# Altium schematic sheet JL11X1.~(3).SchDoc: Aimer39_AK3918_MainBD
size 431 x 279 mm; Revision: 1.2.1; Release Date: 2014-05-28; SchModifyDate: 2020.11.1; PCBVersion: V1.0.0; PCBPartNumber: EVB_PHY_SZ18201; 版本号: V1.0.0
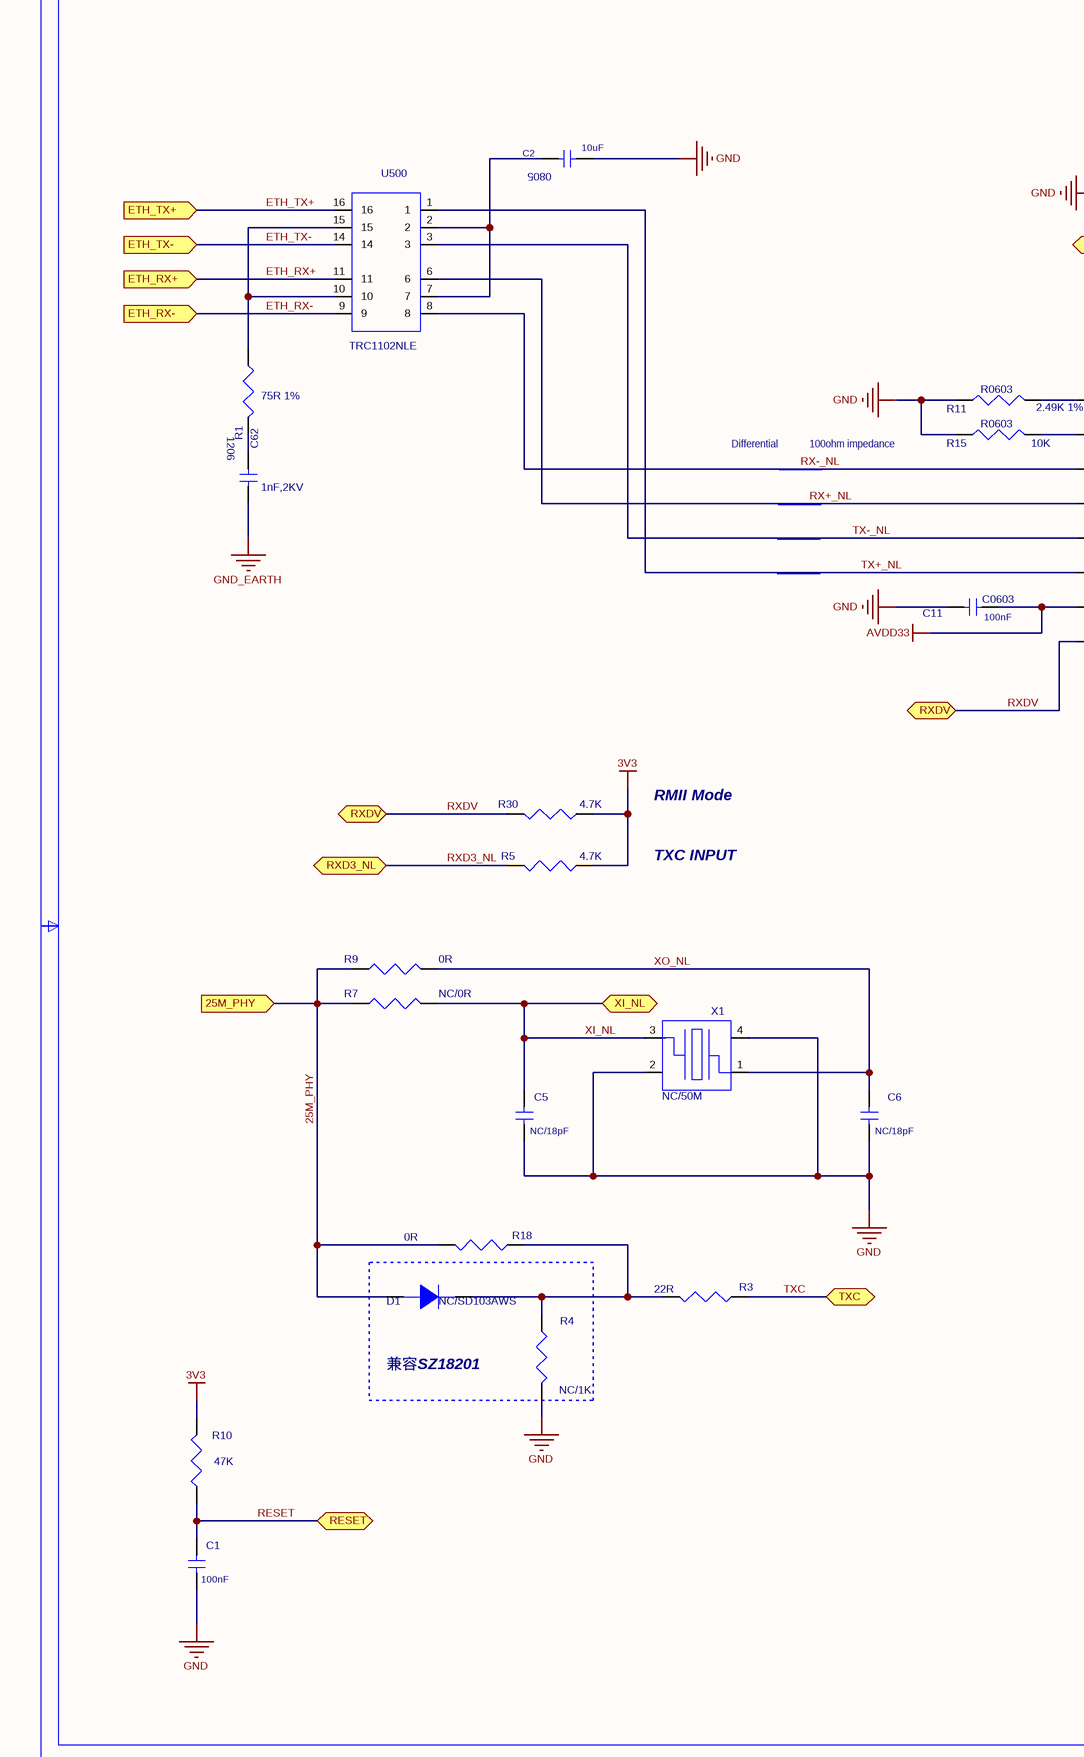
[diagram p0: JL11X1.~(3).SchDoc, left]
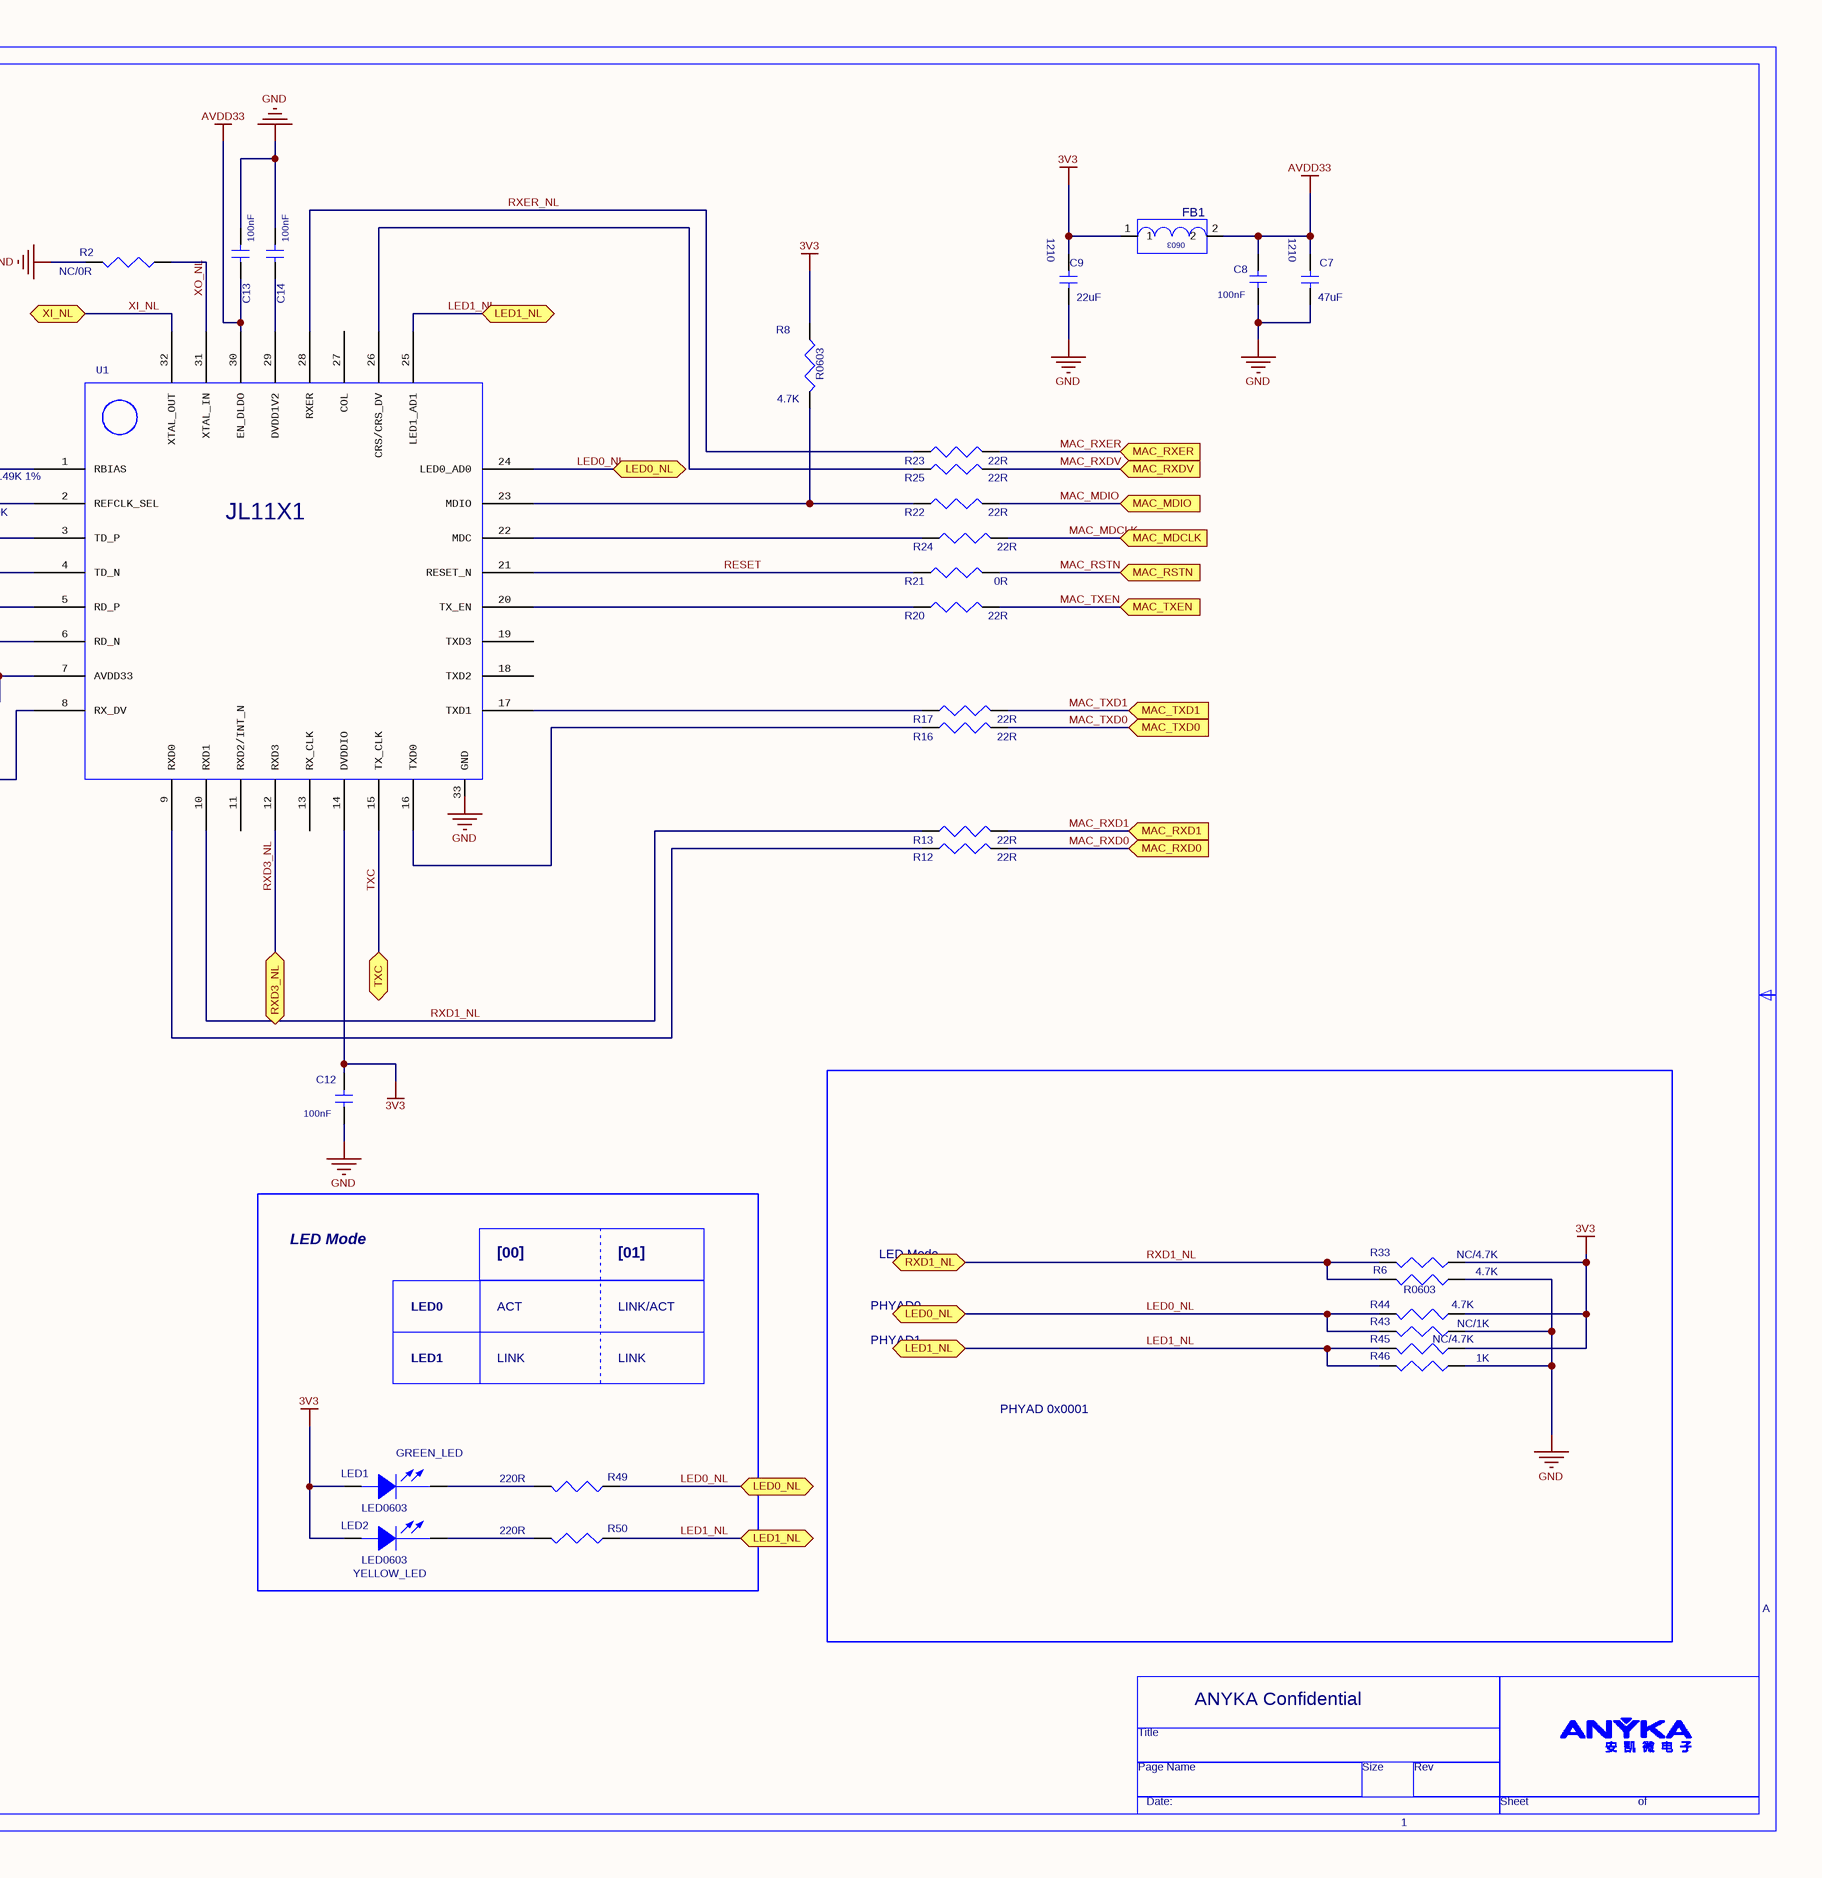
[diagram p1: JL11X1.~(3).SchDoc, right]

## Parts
C1  value 100nF  [C0603]  (hidden comment: C0603)
C2  value 10uF  [C0805]  (hidden comment: C0805)
C5  value NC/18pF  [C0603]  (hidden comment: C0603)
C6  value NC/18pF  [C0603]  (hidden comment: C0603)
C7  value 47uF  [C1210]  (hidden comment: C1210)
C8  value 100nF  [C0603]  (hidden comment: C0603)
C9  value 22uF  [C1210]  (hidden comment: C1210)
C11  C0603  value 100nF  [C0603]
C12  value 100nF  [C0603]  (hidden comment: C0603)
C13  value 100nF  [C0603]  (hidden comment: C0603)
C14  value 100nF  [C0603]  (hidden comment: C0603)
C62  value 1nF,2KV  [C1206]  (hidden comment: C1206)
D1  value NC/SD103AWS  [1N4148_SMD]  (hidden comment: DIODE)
FB1  FB0603  [FB0603]  (value not drawn)
LED1  value GREEN_LED  [LED0603]  (hidden comment: LED0603)
LED2  value YELLOW_LED  [LED0603]  (hidden comment: LED0603)
R1  value 75R 1%  [R0603]  (hidden comment: R0603)
R2  value NC/0R  [R0603]  (hidden comment: R0603)
R3  value 22R  [R0603]  (hidden comment: R0603)
R4  value NC/1K  [R0603]  (hidden comment: R0603)
R5  value 4.7K  [R0603]  (hidden comment: R0603)
R6  R0603  value 4.7K  [R0603]
R7  value NC/0R  [R0603]  (hidden comment: R0603)
R8  R0603  value 4.7K  [R0603]
R9  value 0R  [R0603]  (hidden comment: R0603)
R10  value 47K  [R0603]  (hidden comment: R0603)
R11  R0603  value 2.49K 1%  [R0603]
R12  value 22R  [R0603]  (hidden comment: R0603)
R13  value 22R  [R0603]  (hidden comment: R0603)
R15  R0603  value 10K  [R0603]
R16  value 22R  [R0603]  (hidden comment: R0603)
R17  value 22R  [R0603]  (hidden comment: R0603)
R18  value 0R  [R0603]  (hidden comment: R0603)
R20  value 22R  [R0603]  (hidden comment: R0603)
R21  value 0R  [R0603]  (hidden comment: R0603)
R22  value 22R  [R0603]  (hidden comment: R0603)
R23  value 22R  [R0603]  (hidden comment: R0603)
R24  value 22R  [R0603]  (hidden comment: R0603)
R25  value 22R  [R0603]  (hidden comment: R0603)
R30  value 4.7K  [R0603]  (hidden comment: R0603)
R33  value NC/4.7K  [R0603]  (hidden comment: R0603)
R43  value NC/1K  [R0603]  (hidden comment: R0603)
R44  value 4.7K  [R0603]  (hidden comment: R0603)
R45  value NC/4.7K  [R0603]  (hidden comment: R0603)
R46  value 1K  [R0603]  (hidden comment: R0603)
R49  value 220R  [R0603]  (hidden comment: R0603)
R50  value 220R  [R0603]  (hidden comment: R0603)
U1  JZ1101_QFN32_0MM5_5X5MM  [RTL8201F_QFN32_0MM5_5X5MM]  (value not drawn)
U500  TRC1102NLE  [TRC1102NLE]
X1  value NC/50M  [KSX23]  (hidden comment: KSX23)

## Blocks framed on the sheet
兼容SZ18201: D1 R4

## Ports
25M_PHY, ETH_RX+, ETH_RX-, ETH_TX+, ETH_TX-, LED0_NL (bidir), LED1_NL (bidir), MAC_MDCLK, MAC_MDIO, MAC_RSTN, MAC_RXD0, MAC_RXD1, MAC_RXDV, MAC_RXER, MAC_TXD0 (in), MAC_TXD1 (in), MAC_TXEN (in), RESET (bidir), RXD1_NL (bidir), RXD3_NL (bidir), RXDV (bidir), TXC (bidir), XI_NL (bidir)

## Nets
3V3: C9.1 C12.2 FB1.1 LED1.A LED2.A R5.2 R8.1 R10.2 R30.2 R33.2 R44.2 R45.2 U1.14(DVDDIO)
AVDD33: C7.1 C8.2 C11.2 C13.1 FB1.2 U1.7(AVDD33) U1.30(EN_DLDO)
GND: C1.1 C2.2 C5.1 C6.1 C7.2 C8.1 C9.2 C11.1 C12.1 C13.2 C14.2 R2.1 R4.2 R6.2 R11.1 R15.1 R43.2 R46.2 U1.33(GND) X1.2 X1.4
GND_EARTH: C62.2
25M_PHY: D1.A R7.2 R9.2 R18.2 ; port 25M_PHY
ETH_RX+: U500.11 ; port ETH_RX+
ETH_RX-: U500.9 ; port ETH_RX-
ETH_TX+: U500.16 ; port ETH_TX+
ETH_TX-: U500.14 ; port ETH_TX-
LED0_NL: R43.1 R44.1 R49.1 U1.24(LED0_AD0) ; port LED0_NL
LED1_NL: R45.1 R46.1 R50.1 U1.25(LED1_AD1) ; port LED1_NL
MAC_MDCLK: R24.2 ; port MAC_MDCLK
MAC_MDIO: R22.2 ; port MAC_MDIO
MAC_RSTN: R21.2 ; port MAC_RSTN
MAC_RXD0: R12.2 ; port MAC_RXD0
MAC_RXD1: R13.2 ; port MAC_RXD1
MAC_RXDV: R25.2 ; port MAC_RXDV
MAC_RXER: R23.2 ; port MAC_RXER
MAC_TXD0: R16.2 ; port MAC_TXD0
MAC_TXD1: R17.2 ; port MAC_TXD1
MAC_TXEN: R20.2 ; port MAC_TXEN
RESET: C1.2 R10.1 R21.1 U1.21(RESET_N) ; port RESET
RX+_NL: U1.4(TD_N) U500.6
RX-_NL: U1.3(TD_P) U500.8
RXD1_NL: R6.1 R13.1 R33.1 U1.10(RXD1) ; port RXD1_NL
RXD3_NL: R5.1 U1.12(RXD3) ; port RXD3_NL
RXDV: R30.1 U1.8(RX_DV) ; port RXDV
RXER_NL: R23.1 U1.28(RXER)
TX+_NL: U1.6(RD_N) U500.1
TX-_NL: U1.5(RD_P) U500.3
TXC: R3.1 U1.15(TX_CLK) ; port TXC
XI_NL: C5.2 R7.1 U1.32(XTAL_OUT) X1.3 ; port XI_NL
XO_NL: C6.2 R2.2 R9.1 U1.31(XTAL_IN) X1.1
NetC2_1: C2.1 U500.2 U500.7
NetC14_1: C14.1 U1.29(DVDD1V2)
NetC62_1: C62.1 R1.1
NetD1_K: D1.K R3.2 R4.1 R18.1
NetLED1_K: LED1.K R49.2
NetLED2_K: LED2.K R50.2
NetR1_2: R1.2 U500.10 U500.15
NetR8_2: R8.2 R22.1 U1.23(MDIO)
NetR11_2: R11.2 U1.1(RBIAS)
NetR12_1: R12.1 U1.9(RXD0)
NetR15_2: R15.2 U1.2(REFCLK_SEL)
NetR16_1: R16.1 U1.16(TXD0)
NetR17_1: R17.1 U1.17(TXD1)
NetR20_1: R20.1 U1.20(TX_EN)
NetR24_1: R24.1 U1.22(MDC)
NetR25_1: R25.1 U1.26(CRS/CRS_DV)

Not connected (* = marked no-connect by the designer): U1 11(RXD2/INT_N) 13(RX_CLK) 18(TXD2) 19(TXD3) 27(COL)

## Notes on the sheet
- Differential
- 100ohm impedance
- RMII Mode
- TXC INPUT
- LED Mode
- [00]
- [01]
- LED1
- LED0
- LINK
- ACT
- LINK/ACT
- PHYAD0
- PHYAD1
- PHYAD 0x0001
- A
- ANYKA Confidential
- Page Name
- Title
- Date:
- Size
- Rev
- Sheet
- of
- 1

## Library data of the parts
C1 C8 = C0603: C/C,100nF,25V,+/-5%,0603; Part Number_AK: CC0301040XX; SOURCE_PATH: E:\工作目录\ORCAD原理图库\ORCAD元件库\电容.OLB
C2 = C0805: C/C,10uF,16V,+/-10%,0805; Part Number_AK: CC0501061XX; SOURCE_PATH: E:\工作目录\ORCAD原理图库\ORCAD元件库\电容.OLB
C5 C6 = C0603: C/C,18pF,25V,+/-5%,0603; Part Number_AK: CC0301800XX; SOURCE_PATH: E:\工作目录\ORCAD原理图库\ORCAD元件库\电容.OLB
C7 = C1210: C/C,47uF,10V,+/-5%,1210; Part Number_AK: CC1004761XX; SOURCE_PATH: E:\工作目录\ORCAD原理图库\ORCAD元件库\电容.OLB
C9 = C1210: C/C,22uF,10V,+/-5%,1206; Part Number_AK: CC0602260XX; SOURCE_PATH: E:\工作目录\ORCAD原理图库\ORCAD元件库\电容.OLB
C11-C14 = C0603: SOURCE_PATH: E:\工作目录\ORCAD原理图库\ORCAD元件库\电容.OLB
C62 = C1206: SOURCE_PATH: E:\工作目录\ORCAD原理图库\ORCAD元件库\电容.OLB
D1 = DIODE: 1N4148_SMD( ROUND); PART_NUMBER: XXXXXXXX
FB1 = FB0603: VALUE: BLM18BD601SN1; SOURCE_PATH: E:\工作目录\ORCAD原理图库\ORCAD元件库\磁珠&电感.OLB
LED1 LED2 = LED0603: GREENLED,0603; Part Number_AK: LE03RXX00XX
R1 = R0603: Res,75R,1/10W,+/-1%,0603; Part Number_AK: CR0375R00XX
R2 R7 R9 = R0603: Res,0R,1/10W,+/-5%,0603; Part Number_AK: CR0300000XX
R3 R4 R18 R49 R50 = R0603: Res,220R,1/10W,+/-5%,0603; Part Number_AK: CR0302210XX
R5 R30 R43 R46 = R0603: Res,1K,1/10W,+/-5%,0603; Part Number_AK: CR0301020XX
R6 R33 R44 R45 = R0603: Res,4.7K,1/10W,+/-5%,0603; Part Number_AK: CR0304720XX
R8 R10-R13 R15-R17 R20-R25 = R0603: Res,100K,1/10W,+/-5%,0603; Part Number_AK: CR0301040XX
U1 = JZ1101_QFN32_0MM5_5X5MM: Source_Path: F:\WORK_SPACE\ERIC\RTL8201\RTL8201F\SCHEMATIC\QFN32_RMII_MII\REFERENCE\V1.4\RTL8201F(E)_COLAY_REFERENCE_1.4.DSN; Value: RTL8201F-CG
U500 = TRC1102NLE: Part_RNEfNErNEncNE: NU704; room: ethernet; NC: 4,5,12,13; Source_Path: D:\MOBILE_PROJECT\WINCE\WINCE-7802\LIBRARY1.OLB
X1 = KSX23: Source_Path: L:\PCB_DESIGN_SYSTEM\ALLEGRO\LIB\SCHEMATIC\MISC.OLB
